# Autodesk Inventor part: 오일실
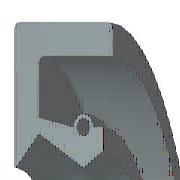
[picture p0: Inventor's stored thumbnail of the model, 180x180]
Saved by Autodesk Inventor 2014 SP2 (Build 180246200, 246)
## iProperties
Created: 2015-11
Part Number: 오일실
Material: 고무
Description: 오일-실
Document SubType Name: Modeling
Standard: KS B 2804
Designer: mdu
Standards Organization: KS
Language: ko-KR
Size Designation: D - 10 20 7
Categories: <MemberInstance><Categories><Category DisplayName="샤프트 부품" InternalName="7f7aeb1f-a693-4053-b835-cee3144e0d98" Mnemonic="SHFT"><Category DisplayName="실링" Intern
Density: 0.93 g/cm^3
Appearance: 고무 - 검은색 - 버전 1.1
Mass: 1.11329 g
Surface Area: 16.3871 cm^2
Volume: 1.19708 cm^3
IsCustomPart: 0
Author: mdu
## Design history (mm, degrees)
revolve "본체" stored, may be unused: angle "d17" = 90 deg
revolve "스프링1" stored, may be unused: angle "d18" = 90 deg
body "Solid1"
sketch "스케치1"
  geometry: L1 (0, 10)-(7, 10); L2 (7, 8.25)-(1.75, 8.25); L3 (1.75, 6.75)-(4.9, 5); L4 (4.9, 5)-(0, 5); L5 (0, 0)-(9.586, 0) reference; L6 (4.9, 5)-(6.3, 5.875); L7 (0, 18)-(0, -3) reference; L8 (-1.941, 0)-(11.507, 0) reference; L9 (4.2, 7.1)-(1.75, 7.59); L10 (1.75, 7.59)-(1.75, 8.25); L11 (0, 10)-(0, 5.088); L12 (4.9, 5)-(0, 5); L13 (1.75, 6.75)-(0.152, 5.028); L14 (7, 10)-(7, 8.25); L15 (5.6, 7.1)-(6.3, 7.1); L16 (6.3, 7.1)-(6.3, 5.875); C1 r 0.455 at (4.9, 7.1); A1 r 0.7 centre (4.9, 7.1) between (5.6, 7.1) and (4.2, 7.1); A2 r 0.088 centre (0.088, 5.088) between (0, 5.088) and (0.152, 5.028); 1 further point
  constraints: 28 end point, 5 horizontal alignment, 5 point on line, 4 point on circle, 4 vertical alignment, 3 centre point, 3 tangent, 2 collinear, 2 horizontal, 2 perpendicular, 1 coincident, 1 parallel
  dimensions: "d0" = 20 diameter of L1 L5 (= SD2); "d1" = 1.75 distance of L1.end L2.start (= SD); "d2" = 0.91 diameter of C1 (= SPDI); "d3" = 1.4 diameter of A1 (= SPDA); "d4" = 10 diameter of L3.end L5 (= NND); "d5" = 13.5 diameter of L3.start L5 (= TKDM); "d7" = 15.18 diameter of L9.end L5 (= TKDM + 0.24 x SWDT); "d8" = 1.75 distance between parallel lines of L11 L10 (= SD); "d9" = 4.9 distance from line of L11 C1.centre (= SPDST); "d10" = 14.2 diameter of C1.centre L5 (= HLDM); "d11" = 0.0875 radius of A2 (= 0.25 x LAB); "d12" = 6.3 distance between parallel lines of L11 L16 (= SDI); "d13" = 11.75 diameter of L6.end L5 (= ABDM); "d14" = 7 distance from line of L11 L1.end (= SWDT)
fillet "모깎기1" dims "d6" = 0.3 (= RR)
other parameters: "SD2" = 20 [user parameter; used in 1 equation term], "SWDT" = 7 [user parameter; used in 2 equation terms], "RR" = 0.3 [user parameter; used in 1 equation term], "SD" = 1.75 [user parameter; used in 2 equation terms], "NND" = 10 [user parameter; used in 1 equation term], "SPDA" = 1.4 [user parameter; used in 1 equation term], "SPDI" = 0.91 [user parameter; used in 1 equation term], "TKDM" = 13.5 [user parameter; used in 2 equation terms], "HLDM" = 14.2 [user parameter; used in 1 equation term], "ABDM" = 11.75 [user parameter; used in 1 equation term], "SDI" = 6.3 [user parameter; used in 1 equation term], "SPDST" = 4.9 [user parameter; used in 1 equation term], "LAB" = 0.35 [user parameter; used in 1 equation term], "d15" = 0, "d16" = 0, "d19" = 0
